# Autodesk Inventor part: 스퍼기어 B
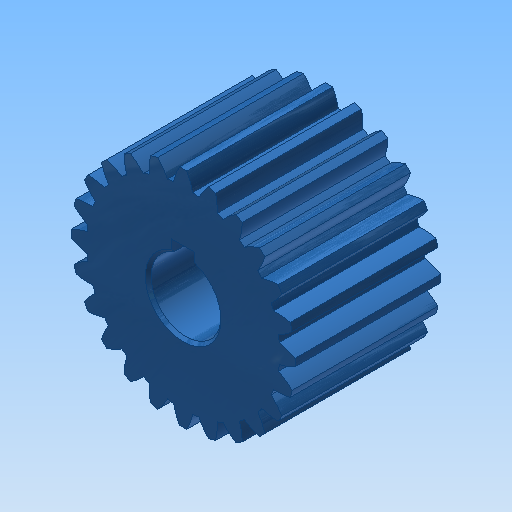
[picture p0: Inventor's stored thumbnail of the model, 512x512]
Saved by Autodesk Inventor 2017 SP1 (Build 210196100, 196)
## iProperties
Created: 2020-04
Part Number: 스퍼기어 B
Material: 강철, 연강
Document SubType Name: Modeling
Designer: mduedu
Categories: <?xml version="1.0" encoding="UTF-16"?> <MemberInstance><Categories><FamilyTemplate><FamilyTemplateParameter ValueType="xs:double" Id="1" ObjectReferenceKey="da
Density: 7.86 g/cm^3
Mass: 175.416 g
Surface Area: 76.8935 cm^2
Volume: 22.3176 cm^3
Appearance: 청록색
CustomPartVersion: 1
Author: mduedu
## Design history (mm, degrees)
sketch "Sketch1"
  geometry: C1 r 19.2 at (0, 0)
  constraints: 1 centre point
  dimensions: "d0" = 38.4 diameter of C1 (= da_da)
extrude "Extrusion1" new body sketch "Sketch1" distance "d1" = 25 (= da_b); taper "d2" = 0 deg
workplane "Work Plane2"
sketch "Sketch2"
  geometry: C1 r 19.2 at (0, 0) reference; C2 r 18 at (0, 0)
  constraints: 1 centre point, 1 coincident
  dimensions: "d3" = 36 diameter of C2 (= da_dw)
feature "피치 지름" sketch "Sketch2" dims "d4" = 10, "d5" = 0
workplane "Work Plane8"
workplane "Work Plane9"
feature "스퍼 기어" dims "da_b" = 25, "da_d" = 36, "da_aw" = 45, "da_da" = 38.4, "da_df" = 33.129, "da_dw" = 36, angle "da_beta" = 0 deg, "da_lefttooth" = 0, "da_righttooth" = 0
sketch "스케치3"
  geometry: L1 (-2, 5.657)-(2, 5.657); L2 (2, 5.657)-(2, 7.8); L3 (2, 7.8)-(-2, 7.8); L4 (-2, 7.8)-(-2, 5.657); A1 r 6 centre (0, 0) between (-2, 5.657) and (2, 5.657); 1 further point
  constraints: 8 end point, 2 parallel, 2 point on circle, 1 centre point, 1 coincident, 1 horizontal, 1 perpendicular
  dimensions: "d49" = 12 diameter of A1; "d51" = 4 distance of L2.end L3.end; "d52" = 13.8 dimension on A1 L3
extrude "돌출2" cut sketch "스케치3" stored distance "d53" = 10; taper "d54" = 0 deg
chamfer "모따기1" distance "d55" = 0.5; stored, may be unused: second distance "d56" = 2, angle "d57" = 45 deg
body "Solid1"
body "Srf1"
other parameters: "d16" = 45 (= da_aw), "d17" = 0, "d34" = 7.5 deg (computed from da_z), "d39" = 0, "d41" = 0, "d43" = 45 (= da_aw), "d46" = 45 (= da_aw), "d47" = 0, "d48" = 0
